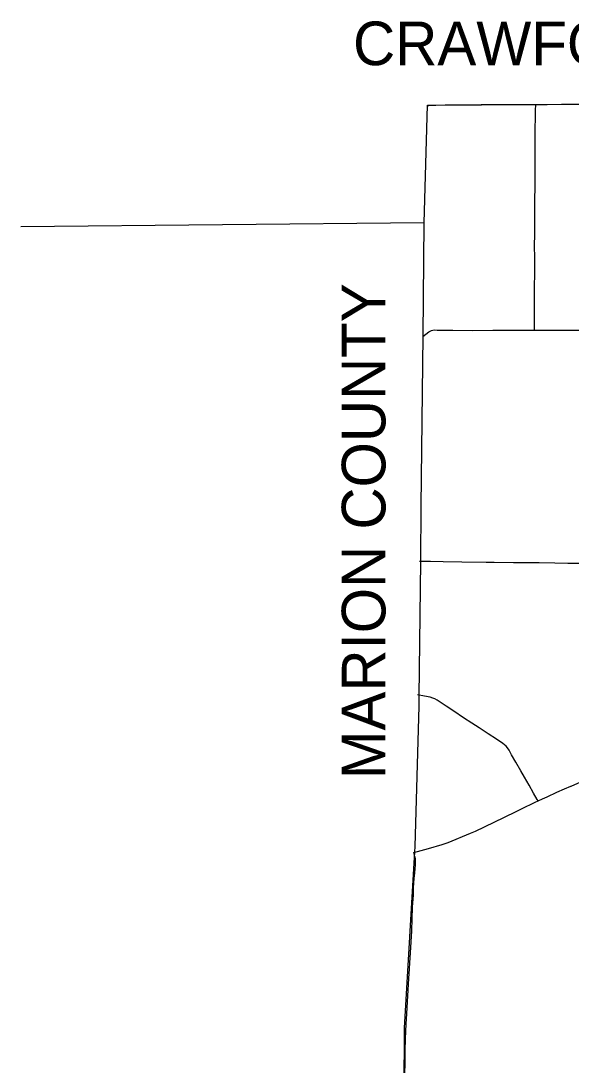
# Model space of a CAD drawing. Extents: x 9078 to 9739, y 4248 to 4966.
# Drawn here: x 9299.3 to 9362.4, y 4831.1 to 4950.8 of the extents above; entities that cross this region are included whole.
import ezdxf

# ---------------------------------------------------------------- set-up
doc = ezdxf.new("R2010")
doc.units = 0
for name, color, linetype in [('GM_X_Adjacent_County', 7, 'Continuous'), ('GM_X_Adjacent_County_Text', 7, 'Continuous'), ('GM_X_County', 7, 'Continuous'), ('GM_X_County_Road', 7, 'Continuous'), ('GM_X_State_Route', 7, 'Continuous'), ('GM_X_Township_Road', 7, 'Continuous')]:
    doc.layers.add(name, color=color, linetype=linetype)

msp = doc.modelspace()

# ---------------------------------------------------------------- linework, layer by layer
at = {"layer": 'GM_X_Adjacent_County'}
msp.add_line((9345.55, 4927.64), (9299.34, 4927.18), dxfattribs=at)
at = {"layer": 'GM_X_County'}
msp.add_lwpolyline([(9343.22, 4820.77), (9343.27, 4835.39), (9344.48, 4855.56), (9344.51, 4856.15), (9344.96, 4872.27), (9344.98, 4873.37), (9345.14, 4888.83), (9345.21, 4895.17), (9345.41, 4914.7), (9345.55, 4927.64), (9345.92, 4941.15), (9358.31, 4941.22), (9378.39, 4941.3)], dxfattribs=at)
at = {"layer": 'GM_X_County_Road'}
for points in [[(9345.96, 4941.08), (9346.06, 4941.1), (9346.23, 4941.12), (9346.47, 4941.14), (9346.88, 4941.15), (9347.95, 4941.16), (9349.02, 4941.18), (9350.25, 4941.19), (9352.08, 4941.2), (9353.29, 4941.2), (9354.19, 4941.21), (9355.09, 4941.21), (9356.49, 4941.21), (9357.88, 4941.21), (9358.3, 4941.21)], [(9358.3, 4941.21), (9358.79, 4941.2), (9359.61, 4941.22), (9361.25, 4941.25), (9364.29, 4941.28), (9366.75, 4941.29), (9368.15, 4941.29), (9369.62, 4941.3), (9371.27, 4941.29), (9372.09, 4941.29), (9373.32, 4941.3), (9374.22, 4941.3), (9375.7, 4941.29), (9377.01, 4941.29), (9378.16, 4941.29), (9378.36, 4941.29)], [(9345.38, 4914.64), (9346.09, 4915.16), (9346.23, 4915.25), (9346.38, 4915.31), (9346.54, 4915.35), (9346.7, 4915.37), (9347.03, 4915.36), (9347.6, 4915.33), (9348.83, 4915.33), (9351.05, 4915.32), (9353.42, 4915.33), (9356.95, 4915.33), (9358.16, 4915.33)], [(9358.16, 4915.33), (9358.84, 4915.33), (9361.38, 4915.33), (9362.44, 4915.34), (9364.57, 4915.34), (9364.79, 4915.33)]]:
    msp.add_lwpolyline(points, dxfattribs=at)
at = {"layer": 'GM_X_State_Route'}
for points in [[(9356.69, 4860.47), (9358.27, 4861.24), (9358.58, 4861.39), (9359.08, 4861.64), (9359.61, 4861.87), (9360.73, 4862.38), (9361.63, 4862.77), (9362.35, 4863.08), (9362.38, 4863.1), (9363.15, 4863.43), (9363.95, 4863.78), (9364.04, 4863.82), (9365.01, 4864.24), (9365.61, 4864.5), (9366, 4864.68), (9366.81, 4865.04), (9367.51, 4865.34), (9367.87, 4865.5), (9368.43, 4865.73), (9368.54, 4865.78), (9368.82, 4865.9), (9369.04, 4865.98), (9369.28, 4866.09)], [(9350.85, 4857.7), (9351.4, 4857.93), (9353.54, 4858.96), (9355.99, 4860.13), (9356.69, 4860.47)], [(9344.35, 4855.46), (9344.76, 4855.59), (9346.04, 4855.95), (9347.59, 4856.4), (9348.3, 4856.63), (9350.85, 4857.7)]]:
    msp.add_lwpolyline(points, dxfattribs=at)
at = {"layer": 'GM_X_Township_Road'}
for points in [[(9358.16, 4915.33), (9358.16, 4915.5), (9358.17, 4916.73), (9358.18, 4919.93), (9358.2, 4922.23), (9358.21, 4923.29), (9358.2, 4923.86), (9358.19, 4924.77), (9358.2, 4926.57), (9358.21, 4929.69), (9358.24, 4932.39), (9358.25, 4935.02), (9358.27, 4937.48), (9358.3, 4940.67), (9358.31, 4941.08), (9358.3, 4941.21)], [(9345.01, 4888.89), (9346.25, 4888.87), (9347.73, 4888.85), (9349.86, 4888.81), (9352.65, 4888.76), (9353.55, 4888.75), (9355.76, 4888.73), (9358.71, 4888.7), (9360.52, 4888.68), (9361.99, 4888.66), (9363.3, 4888.65), (9363.88, 4888.65), (9364.29, 4888.64), (9364.41, 4888.64)], [(9358.07, 4862.29), (9357.55, 4863.21), (9357.02, 4864.13), (9356.61, 4864.84), (9356.03, 4865.83), (9355.55, 4866.69), (9355.27, 4867.19), (9355.09, 4867.46), (9354.93, 4867.65), (9354.75, 4867.81), (9354.56, 4867.97), (9353.81, 4868.47), (9352.85, 4869.09), (9351.82, 4869.76), (9351, 4870.3), (9350.04, 4870.93), (9348.94, 4871.66), (9348.06, 4872.25), (9347.03, 4872.93), (9346.75, 4873.09), (9346.53, 4873.18), (9346.21, 4873.27), (9345.57, 4873.39), (9344.79, 4873.55)], [(9358.58, 4861.39), (9358.48, 4861.57), (9358.07, 4862.29)], [(9343.34, 4828.72), (9343.38, 4832.74), (9343.4, 4834.13), (9343.48, 4835.85), (9343.55, 4837), (9343.63, 4838.39), (9343.66, 4839.05), (9343.78, 4841.02), (9343.86, 4842.16), (9343.9, 4842.82), (9343.97, 4843.96), (9344.11, 4846.5), (9344.17, 4847.89), (9344.22, 4849.21), (9344.3, 4850.6), (9344.33, 4851.42), (9344.41, 4852.48), (9344.47, 4853.13), (9344.54, 4854.11), (9344.55, 4854.53), (9344.53, 4854.77), (9344.48, 4855.02), (9344.44, 4855.19), (9344.35, 4855.46)]]:
    msp.add_lwpolyline(points, dxfattribs=at)

# ---------------------------------------------------------------- texts
at = {"layer": 'GM_X_Adjacent_County_Text'}
msp.add_text('CRAWFORD COUNTY', height=5, dxfattribs=at).set_placement((9337.39, 4945.72))
msp.add_text('MARION COUNTY', height=5, rotation=90, dxfattribs=at).set_placement((9341.1, 4863.89))

doc.saveas('drawing.dxf')
